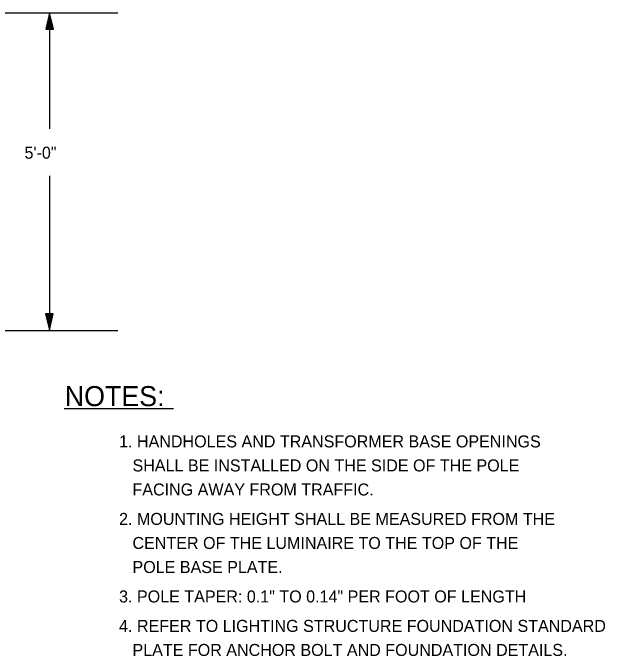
# Model space of a CAD drawing. Extents: x 9989.4 to 10000.1, y 10000.3 to 10010.3.
# Drawn here: x 9992.804 to 9995.76, y 10002.416 to 10005.627 of the extents above; entities that cross this region are included whole.
import ezdxf

# ---------------------------------------------------------------- set-up
doc = ezdxf.new("R2010")
doc.units = 0
doc.layers.add('DETL-DIMS', color=7, linetype='Continuous')
doc.layers.add('DETL-NOTE', color=7, linetype='Continuous')

msp = doc.modelspace()

# ---------------------------------------------------------------- linework, layer by layer
at = {"layer": 'DETL-DIMS'}
for p, q in [((9992.078, 10005.627), (9993.3279, 10005.627)), ((9992.9872, 10005.627), (9992.9872, 10005.0488)), ((9992.9872, 10004.8137), (9992.9872, 10004.043)), ((9992.2692, 10004.042), (9993.3279, 10004.042))]:
    msp.add_line(p, q, dxfattribs=at)
for points in [[(9993.0072, 10005.545), (9992.9872, 10005.627), (9992.9692, 10005.545), (9993.0072, 10005.545)], [(9993.0042, 10005.547), (9992.9872, 10005.619), (9992.9712, 10005.547), (9993.0042, 10005.547)], [(9993.0022, 10005.549), (9992.9872, 10005.611), (9992.9732, 10005.549), (9993.0022, 10005.549)], [(9993.0002, 10005.55), (9992.9872, 10005.603), (9992.9762, 10005.55), (9993.0002, 10005.55)], [(9992.9982, 10005.552), (9992.9872, 10005.596), (9992.9782, 10005.552), (9992.9982, 10005.552)], [(9992.9952, 10005.554), (9992.9872, 10005.587), (9992.9802, 10005.554), (9992.9952, 10005.554)], [(9992.9932, 10005.556), (9992.9872, 10005.58), (9992.9822, 10005.556), (9992.9932, 10005.556)], [(9992.9912, 10005.557), (9992.9882, 10005.572), (9992.9842, 10005.557), (9992.9912, 10005.557)], [(9992.9892, 10005.559), (9992.9882, 10005.564), (9992.9872, 10005.559), (9992.9892, 10005.559)], [(9992.9672, 10004.125), (9992.9872, 10004.043), (9993.0052, 10004.125), (9992.9672, 10004.125)], [(9992.9702, 10004.123), (9992.9872, 10004.051), (9993.0032, 10004.123), (9992.9702, 10004.123)], [(9992.9722, 10004.121), (9992.9872, 10004.059), (9993.0012, 10004.121), (9992.9722, 10004.121)], [(9992.9742, 10004.12), (9992.9872, 10004.067), (9992.9982, 10004.12), (9992.9742, 10004.12)], [(9992.9762, 10004.118), (9992.9872, 10004.075), (9992.9962, 10004.118), (9992.9762, 10004.118)], [(9992.9792, 10004.116), (9992.9872, 10004.083), (9992.9942, 10004.116), (9992.9792, 10004.116)], [(9992.9812, 10004.114), (9992.9872, 10004.09), (9992.9922, 10004.114), (9992.9812, 10004.114)], [(9992.9832, 10004.113), (9992.9862, 10004.098), (9992.9902, 10004.113), (9992.9832, 10004.113)], [(9992.9852, 10004.111), (9992.9862, 10004.106), (9992.9872, 10004.111), (9992.9852, 10004.111)]]:
    msp.add_lwpolyline(points, dxfattribs=at)
at = {"layer": 'DETL-NOTE'}
msp.add_line((9993.0607, 10003.6518), (9993.6064, 10003.6518), dxfattribs=at)

# ---------------------------------------------------------------- texts
for s, height, p in [('5\'-0"', 0.06, (9992.8625, 10004.8991)), ('NOTES:', 0.1, (9993.0634, 10003.664)), ('1. HANDHOLES AND TRANSFORMER BASE OPENINGS', 0.06, (9993.3344, 10003.458)), ('   SHALL BE INSTALLED ON THE SIDE OF THE POLE', 0.06, (9993.3344, 10003.338)), ('   FACING AWAY FROM TRAFFIC.', 0.06, (9993.3344, 10003.218)), ('2. MOUNTING HEIGHT SHALL BE MEASURED FROM THE', 0.06, (9993.3344, 10003.071)), ('   CENTER OF THE LUMINAIRE TO THE TOP OF THE ', 0.06, (9993.3344, 10002.951)), ('   POLE BASE PLATE.', 0.06, (9993.3344, 10002.831)), ('3. POLE TAPER: 0.1" TO 0.14" PER FOOT OF LENGTH', 0.06, (9993.3344, 10002.684)), ('4. REFER TO LIGHTING STRUCTURE FOUNDATION STANDARD ', 0.06, (9993.3344, 10002.537)), ('   PLATE FOR ANCHOR BOLT AND FOUNDATION DETAILS.', 0.06, (9993.3344, 10002.417))]:
    msp.add_text(s, height=height, dxfattribs=at).set_placement(p)

doc.saveas('drawing.dxf')
